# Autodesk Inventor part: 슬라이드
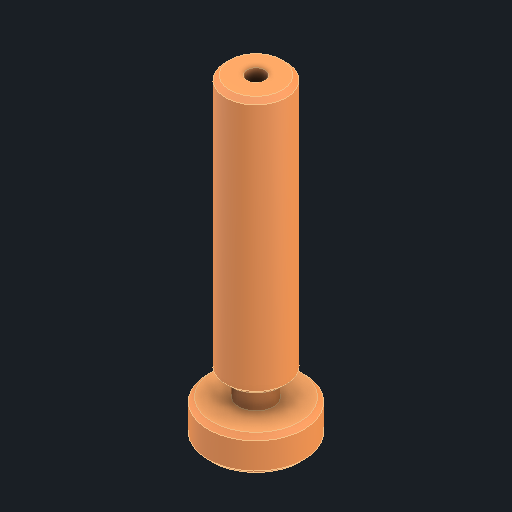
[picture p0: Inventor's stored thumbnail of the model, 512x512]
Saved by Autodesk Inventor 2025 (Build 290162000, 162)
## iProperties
Created: 2025-08
Part Number: 슬라이드
Material: 강철, 연강
Document SubType Name: Modeling
Designer: infra002
Density: 7.86 g/cm^3
Appearance: 기본값
Author: jhkim
Sending System: Autodesk Inventor 2026
Preprocessor: ST-DEVELOPER v20.1
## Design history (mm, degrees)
feature "솔리드1"
node "솔리드2"
